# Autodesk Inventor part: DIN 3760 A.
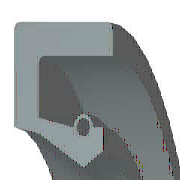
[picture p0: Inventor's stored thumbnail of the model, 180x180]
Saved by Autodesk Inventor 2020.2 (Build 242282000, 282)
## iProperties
Manager: www.cadconsulting.pl
Company: Fabian Stasiak CAD Consulting
Created: 2006-03
Part Number: DIN 3760 A.
Material: TS
Description: Pierścień uszczelniający 25x35x7-NBR
Vendor: Autodesk Inc.
Document SubType Name: Modeling
Standard: DIN 3760
Designer: F.Stasiak
Standards Organization: DIN
Language: pl-PL
Size Designation: A - 25 x 35 x 7 - NBR
Categories: <MemberInstance Version="R10.0.0"><Categories><Category DisplayName="Części wałów" InternalName="7f7aeb1f-a693-4053-b835-cee3144e0d98" Mnemonic="SHFT"><Category
Stock Number: PFP 1Z25357
Project: Przekładnia X51
Density: 1.06 g/cm^3
Appearance: Tworzywo sztuczne (czarne)
Author: F.Stasiak
Subject: Zbiór ćwiczeń. Autodesk Inventor 2020. Kurs podstawowy
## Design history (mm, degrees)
revolve "Bryła" stored, may be unused: angle "d17" = 90 deg
revolve "Sprężyna1" stored, may be unused: angle "d18" = 90 deg
node "Bryła1"
node "Korpusy bryłowe"
node "Korpusy powierzchniowe"
sketch "Szkic1"
  geometry: L1 (0, 17.5)-(7, 17.5); L2 (7, 17.5)-(7, 16.25); L3 (7, 16.25)-(1.75, 16.25); L4 (0, 17.5)-(0, 14.6); L5 (0, 14.6)-(1.75, 14.25); L6 (1.75, 14.25)-(4.9, 12.5); L7 (4.9, 12.5)-(0, 12.5); L8 (6.3, 13.375)-(6.3, 14.6); L9 (0, 0)-(9.586, 0) reference; L10 (4.9, 12.5)-(6.3, 13.375); L11 (0, 19.5)-(0, -1.5) reference; L12 (-0.959, 0)-(12.461, 0) reference; L13 (4.2, 14.6)-(1.75, 15.09); L14 (1.75, 15.09)-(1.75, 16.25); L15 (6.3, 14.6)-(5.6, 14.6); C1 r 0.455 at (4.9, 14.6); A1 r 0.7 centre (4.9, 14.6) between (5.6, 14.6) and (4.2, 14.6)
  constraints: 26 end point, 5 horizontal alignment, 4 perpendicular, 2 centre point, 2 collinear, 2 horizontal, 2 parallel, 2 point on circle, 2 point on line, 2 vertical alignment, 1 coincident
  dimensions: "d0" = 35 diameter of L1 L9 (= SD2); "d1" = 26.75 diameter of L8.start L9 (= ABDM); "d2" = 1.25 distance of L1.end L2.end (computed from SD); "d3" = 0.91 diameter of C1 (= SPDI); "d4" = 1.4 diameter of A1 (= SPDA); "d5" = 25 diameter of L6.end L9 (= NND); "d6" = 28.5 diameter of L5.end L9 (= TKDM); "d7" = 29.2 diameter of L4.end L9 (= HLDM); "d8" = 4.9 distance from line of C1.centre L4 (= SPDST); "d9" = 6.3 distance between parallel lines of L8 L4 (= SDI); "d10" = 7 distance between parallel lines of L2 L4 (= SWDT); "d12" = 1.75 distance between parallel lines of L14 L4 (= SD)
fillet "Zaokrąglenie1" dims "d11" = 0.3 (= RR)
other parameters: "SD2" = 35 [user parameter; used in 1 equation term], "SWDT" = 7 [user parameter; used in 1 equation term], "RR" = 0.3 [user parameter; used in 1 equation term], "SD" = 1.75 [user parameter; used in 2 equation terms], "NND" = 25 [user parameter; used in 1 equation term], "SPDA" = 1.4 [user parameter; used in 1 equation term], "SPDI" = 0.91 [user parameter; used in 1 equation term], "TKDM" = 28.5 [user parameter; used in 1 equation term], "HLDM" = 29.2 [user parameter; used in 1 equation term], "ABDM" = 26.75 [user parameter; used in 1 equation term], "SDI" = 6.3 [user parameter; used in 1 equation term], "SPDST" = 4.9 [user parameter; used in 1 equation term], "d13" = 0, "d14" = 0, "d15" = 0, "LAB" = 0.35 [user parameter]
